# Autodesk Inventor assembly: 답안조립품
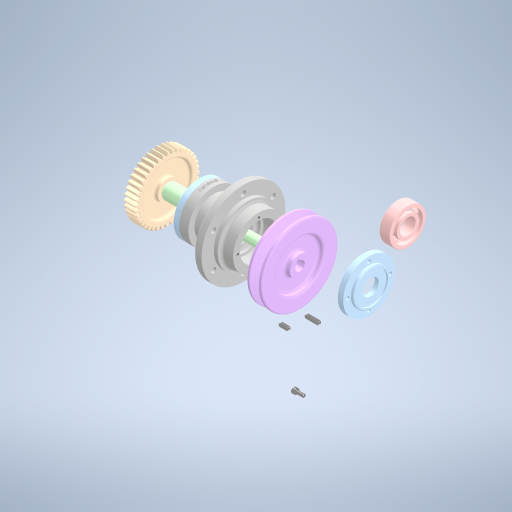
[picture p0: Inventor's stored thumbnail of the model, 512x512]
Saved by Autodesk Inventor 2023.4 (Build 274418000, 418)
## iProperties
Created: 2024-04
Part Number: 답안조립품
Document SubType Name: Assembly
Designer: Edu03
Author: Edu03
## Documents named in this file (14)
- C:\Users\Edu03\Desktop\740404V1004\답안조립품.iam
- C:\Users\Edu03\Desktop\740404V1004\V-벨트풀리\V-벨트풀리.ipt
- C:\Users\Edu03\Desktop\740404V1004\깊은 홈 볼 베어링 6204\깊은 홈 볼 베어링 6204.ipt
- C:\Users\Edu03\Desktop\740404V1004\스프링와셔 M12\스프링와셔 M12.ipt
- C:\Users\Edu03\Desktop\740404V1004\오일 실 20 32 5\오일 실 20 32 5.ipt
- C:\Users\Edu03\Desktop\740404V1004\육각 소켓 머리 볼트 M4x10\육각 소켓 머리 볼트 M4x10.ipt
- C:\Users\Edu03\Desktop\740404V1004\육각너트 M12x1\육각너트 M12x1.ipt
- C:\Users\Edu03\Desktop\740404V1004\축\축.ipt
- C:\Users\Edu03\Desktop\740404V1004\커버\커버.ipt
- C:\Users\Edu03\Desktop\740404V1004\평와셔 M12\평와셔 M12.ipt
- C:\Users\Edu03\Desktop\740404V1004\평행키 4x4x12\평행키 4x4x12.ipt
- C:\Users\Edu03\Desktop\740404V1004\평행키 4x4x18\평행키 4x4x18.ipt
- C:\Users\Edu03\Desktop\740404V1004\본체.ipt
- C:\Users\Edu03\Desktop\740404V1004\스퍼기어.ipt
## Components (1 placed, 1 different names)
1. V-벨트풀리:1
